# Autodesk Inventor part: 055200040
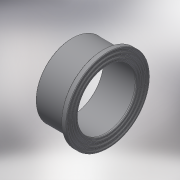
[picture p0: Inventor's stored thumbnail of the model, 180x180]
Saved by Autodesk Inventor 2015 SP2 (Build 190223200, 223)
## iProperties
Created: 2017-10
Part Number: 055200040
Material: Generic
Description: PLASSON FLANGE(FLAT GASKET)C 40
Document SubType Name: Modeling
Designer: KIM
Density: 1 g/cm^3
Appearance: Default
Author: KIM
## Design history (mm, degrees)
derived "055200.ipt"
feature "Solid1::055200.ipt"
tag "TaggingFeature1"
body "Solid1"
other parameters: "d0" = 29, "d3" = 38, "d4" = 8, "d5" = 26, "d6" = 61, "d8" = 2.4, "d11" = 0.4, "d12" = 1.2, "E_1" = 61, "l_" = 26, "B_" = 8, "H_" = 29, "d14" = 11.5
